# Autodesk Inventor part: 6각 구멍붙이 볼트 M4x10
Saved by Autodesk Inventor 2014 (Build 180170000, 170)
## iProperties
Created: 2025-12
Part Number: 6각 구멍붙이 볼트 M4x10
Material: 일반
Document SubType Name: Modeling
Designer: dg
Density: 1 g/cm^3
Appearance: 기본값
Author: dg
Author: jhkim
Description: 6각머리 태핑 나사
Creation Date: 2025-11-19
Sending System: Autodesk Inventor 2026
Preprocessor: ST-DEVELOPER v20.1
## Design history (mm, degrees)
node "6각 구멍붙이 볼트 M4x101"
body "Solid1"
node "기준1"
